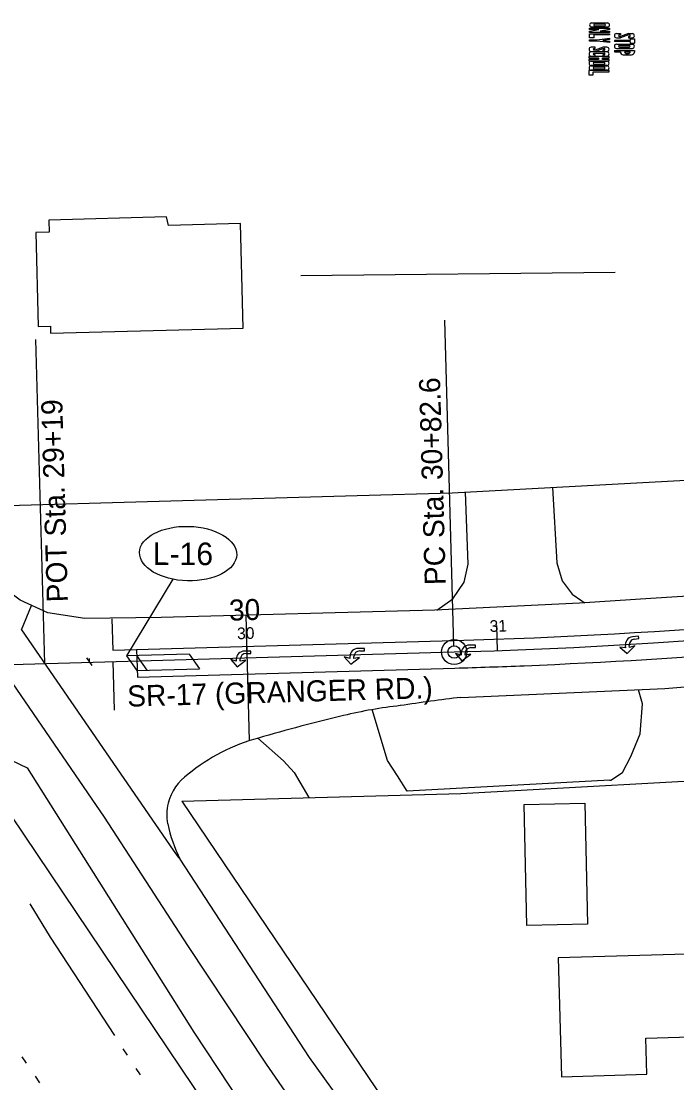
# Model space of a CAD drawing. Extents: x -2233 to 187241, y 4582 to 150524.
# Drawn here: x 103070.3 to 103332, y 58193.5 to 58617.2 of the extents above; entities that cross this region are included whole.
import ezdxf

# ---------------------------------------------------------------- set-up
doc = ezdxf.new("R2010")
doc.units = 0
for name, color, linetype in [('BLDG', 7, 'Continuous'), ('GE_X_CL_100', 7, 'Continuous'), ('GE_X_CL_20', 7, 'Continuous'), ('GE_X_CL_2000', 7, 'Continuous'), ('GE_X_CL_50', 7, 'Continuous'), ('PM_P_Cells', 7, 'Continuous'), ('PM_P_Channelizing_Line', 7, 'Continuous'), ('PM_P_CL_Double_Solid', 7, 'Continuous'), ('PM_P_Stop_Line', 7, 'Continuous'), ('PM_X_CL_Double_Solid', 7, 'Continuous'), ('PV_X_Driveway', 7, 'Continuous'), ('ROAD', 7, 'Continuous'), ('RW_X_Fee_RW', 7, 'Continuous'), ('SC_Scratch2', 7, 'Continuous'), ('SG_P_Detection', 7, 'Continuous'), ('SH_Data', 7, 'Continuous'), ('WATER', 7, 'Continuous')]:
    doc.layers.add(name, color=color, linetype=linetype)

msp = doc.modelspace()

# ---------------------------------------------------------------- linework, layer by layer
at = {"layer": 'BLDG'}
for points in [[(103157.82, 58536.46), (103129.03, 58535.72), (103128.3, 58539.08), (103081.27, 58537.87), (103081.4, 58533.01), (103076.1, 58532.87), (103077.07, 58495.34), (103081.93, 58495.47), (103081.99, 58492.72), (103158.9, 58494.7)], [(103295.24, 58305.14), (103296.36, 58256.85), (103272.17, 58256.29), (103271.05, 58304.59)], [(103286.01, 58195.87), (103320.03, 58196.88), (103319.61, 58211.34), (103355.42, 58212.39), (103354.45, 58245.4), (103284.62, 58243.35)]]:
    msp.add_lwpolyline(points, close=True, dxfattribs=at)
at = {"layer": 'GE_X_CL_100'}
for p, q in [((103243.02, 58367.96), (103239.36, 58497.89)), ((103079.68, 58360.85), (103076.03, 58490.12)), ((103260.46, 58366.01), (103260.1, 58376.01)), ((103160.5, 58363.13), (103160.22, 58373.12)), ((103097.52, 58361.35), (103097.48, 58362.9))]:
    msp.add_line(p, q, dxfattribs=at)
msp.add_circle((103243.1, 58365.46), 5, dxfattribs=at)
at = {"layer": 'GE_X_CL_20'}
for q in [(103243.1, 58365.46), (103103.31, 58299.51)]:
    msp.add_line((103061.64, 58360.34), q, dxfattribs=at)
msp.add_arc((103178.49, 60656.39), 2291.85, 271.61534, 297.032, dxfattribs=at)
at = {"layer": 'GE_X_CL_2000'}
for q in [(103243.1, 58365.46), (103103.31, 58299.51)]:
    msp.add_line((103061.64, 58360.34), q, dxfattribs=at)
msp.add_lwpolyline([(103103.31, 58299.51), (103136.59, 58248.24), (103168.03, 58200.95), (103200, 58154.75)], dxfattribs=at)
msp.add_arc((103178.49, 60656.39), 2291.85, 271.61534, 297.032, dxfattribs=at)
at = {"layer": 'GE_X_CL_50'}
for p, q in [((103260.46, 58366.01), (103260.28, 58371.01)), ((103160.5, 58363.13), (103160.36, 58368.13))]:
    msp.add_line(p, q, dxfattribs=at)
msp.add_circle((103243.1, 58365.46), 2.5, dxfattribs=at)
at = {"layer": 'PM_P_Cells'}
for p, q in [((103297.98, 58616.57), (103299.15, 58616.57)), ((103299.15, 58616.57), (103299.15, 58616.07)), ((103299.15, 58616.07), (103299.15, 58616.57)), ((103299.15, 58616.57), (103303.15, 58616.57)), ((103303.15, 58616.07), (103303.15, 58616.57)), ((103303.15, 58616.57), (103304.31, 58616.57)), ((103303.15, 58616.57), (103303.15, 58616.07)), ((103297.15, 58613.9), (103297.15, 58614.4)), ((103297.15, 58614.4), (103305.15, 58614.4)), ((103297.15, 58613.24), (103300.9, 58613.9)), ((103300.9, 58613.9), (103297.15, 58613.9)), ((103297.15, 58612.74), (103297.15, 58613.24)), ((103305.15, 58612.74), (103297.15, 58612.74)), ((103297.15, 58612.65), (103297.15, 58612.65)), ((103304.31, 58614.9), (103297.98, 58614.9)), ((103303.15, 58616.07), (103299.15, 58616.07)), ((103299.15, 58615.4), (103303.15, 58615.4)), ((103305.15, 58613.9), (103301.4, 58613.24)), ((103301.4, 58613.24), (103305.15, 58613.24)), ((103305.15, 58614.4), (103305.15, 58613.9)), ((103305.15, 58613.24), (103305.15, 58612.74)), ((103305.15, 58612.65), (103305.15, 58612.65)), ((103307.9, 58612.28), (103309.49, 58612.28)), ((103309.49, 58612.28), (103309.49, 58611.78)), ((103312.72, 58612.28), (103309.49, 58611.11)), ((103312.72, 58612.28), (103314.24, 58612.28)), ((103297.15, 58610.57), (103297.15, 58612.24)), ((103297.15, 58612.24), (103305.15, 58612.24)), ((103298.81, 58610.57), (103297.15, 58610.57)), ((103297.15, 58609.32), (103297.15, 58609.82)), ((103297.15, 58609.82), (103300.15, 58609.82)), ((103300.15, 58609.32), (103297.15, 58609.32)), ((103305.15, 58611.74), (103298.81, 58611.74)), ((103298.81, 58611.74), (103298.81, 58610.57)), ((103300.15, 58609.82), (103305.15, 58610.4)), ((103305.15, 58608.74), (103300.15, 58609.32)), ((103305.15, 58609.9), (103302.48, 58609.57)), ((103302.48, 58609.57), (103305.15, 58609.24)), ((103305.15, 58612.24), (103305.15, 58611.74)), ((103305.15, 58610.4), (103305.15, 58609.9)), ((103305.15, 58609.24), (103305.15, 58608.74)), ((103313.4, 58609.57), (103307.07, 58609.57)), ((103307.07, 58609.57), (103307.07, 58609.07)), ((103313.4, 58609.07), (103307.07, 58609.07)), ((103307.07, 58608.07), (103307.07, 58608.07)), ((103307.9, 58610.61), (103309.49, 58610.61)), ((103309.07, 58611.78), (103309.49, 58611.78)), ((103309.07, 58611.11), (103309.49, 58611.11)), ((103312.65, 58611.78), (103309.49, 58610.61)), ((103312.65, 58611.78), (103313.07, 58611.78)), ((103312.65, 58611.11), (103312.65, 58610.61)), ((103312.65, 58611.11), (103313.07, 58611.11)), ((103312.65, 58610.61), (103314.24, 58610.61)), ((103313.4, 58610.15), (103315.07, 58610.15)), ((103313.4, 58610.15), (103313.4, 58609.57)), ((103313.4, 58609.07), (103313.4, 58608.49)), ((103313.4, 58608.49), (103315.07, 58608.49)), ((103315.07, 58610.15), (103315.07, 58608.49)), ((103315.07, 58608.07), (103315.07, 58608.07)), ((103299.35, 58606.86), (103297.77, 58606.86)), ((103297.77, 58605.19), (103299.35, 58605.19)), ((103304.1, 58604.99), (103297.77, 58604.99)), ((103298.93, 58606.36), (103299.35, 58606.36)), ((103299.35, 58605.69), (103298.93, 58605.69)), ((103298.93, 58604.49), (103302.93, 58604.49)), ((103299.35, 58603.82), (103298.93, 58603.82)), ((103302.58, 58606.86), (103299.35, 58605.69)), ((103299.35, 58606.36), (103299.35, 58606.86)), ((103299.35, 58605.19), (103302.52, 58606.36)), ((103299.35, 58603.32), (103299.35, 58603.82)), ((103302.52, 58606.36), (103302.93, 58606.36)), ((103302.52, 58605.69), (103302.52, 58605.19)), ((103302.93, 58605.69), (103302.52, 58605.69)), ((103302.52, 58605.19), (103304.1, 58605.19)), ((103302.52, 58603.82), (103302.52, 58603.32)), ((103302.93, 58603.82), (103302.52, 58603.82)), ((103304.1, 58606.86), (103302.58, 58606.86)), ((103307.07, 58605.53), (103315.07, 58605.53)), ((103307.07, 58605.53), (103307.07, 58605.03)), ((103307.07, 58605.03), (103309.49, 58605.03)), ((103307.9, 58608.03), (103314.24, 58608.03)), ((103307.9, 58606.36), (103314.24, 58606.36)), ((103309.07, 58607.53), (103313.07, 58607.53)), ((103309.07, 58606.86), (103313.07, 58606.86)), ((103309.49, 58605.03), (103309.49, 58605.03)), ((103310.64, 58603.86), (103313.91, 58603.86)), ((103311.15, 58605.03), (103311.15, 58605.03)), ((103311.15, 58605.03), (103313.4, 58605.03)), ((103311.81, 58604.36), (103312.74, 58604.36)), ((103313.4, 58605.03), (103313.4, 58605.02)), ((103315.07, 58605.53), (103315.07, 58604.89)), ((103304.93, 58603.12), (103296.93, 58603.12)), ((103296.93, 58603.12), (103296.93, 58602.62)), ((103296.93, 58602.62), (103300.68, 58602.62)), ((103300.68, 58601.96), (103296.93, 58601.96)), ((103296.93, 58601.96), (103296.93, 58601.46)), ((103296.93, 58601.46), (103304.93, 58601.46)), ((103296.93, 58601.36), (103296.93, 58601.36)), ((103297.77, 58603.32), (103299.35, 58603.32)), ((103297.77, 58601.26), (103298.93, 58601.26)), ((103304.1, 58599.59), (103297.77, 58599.59)), ((103298.93, 58601.26), (103298.93, 58600.76)), ((103298.93, 58601.26), (103302.94, 58601.26)), ((103298.93, 58600.76), (103298.93, 58601.26)), ((103302.97, 58600.76), (103298.93, 58600.76)), ((103298.93, 58600.09), (103302.94, 58600.09)), ((103300.68, 58602.62), (103300.68, 58601.96)), ((103302.35, 58601.96), (103302.35, 58602.62)), ((103302.35, 58602.62), (103304.93, 58602.62)), ((103304.93, 58601.96), (103302.35, 58601.96)), ((103302.52, 58603.32), (103304.1, 58603.32)), ((103302.94, 58601.26), (103304.1, 58601.26)), ((103302.94, 58600.76), (103302.94, 58601.26)), ((103302.94, 58601.26), (103302.94, 58600.76)), ((103304.93, 58602.62), (103304.93, 58603.12)), ((103304.93, 58601.46), (103304.93, 58601.96)), ((103304.93, 58601.36), (103304.93, 58601.36)), ((103304.93, 58597.52), (103296.93, 58597.52)), ((103296.93, 58597.52), (103296.93, 58595.86)), ((103296.93, 58595.86), (103298.6, 58595.86)), ((103297.77, 58599.39), (103298.93, 58599.39)), ((103304.1, 58597.72), (103297.77, 58597.72)), ((103298.6, 58595.86), (103298.6, 58597.02)), ((103298.6, 58597.02), (103304.93, 58597.02)), ((103298.93, 58599.39), (103298.93, 58598.89)), ((103298.93, 58599.39), (103302.93, 58599.39)), ((103298.93, 58598.89), (103298.93, 58599.39)), ((103302.93, 58598.89), (103298.93, 58598.89)), ((103298.93, 58598.22), (103302.93, 58598.22)), ((103302.93, 58599.39), (103304.1, 58599.39)), ((103302.93, 58598.89), (103302.93, 58599.39)), ((103302.93, 58599.39), (103302.93, 58598.89)), ((103304.93, 58597.02), (103304.93, 58597.52)), ((103316.7, 58371.81), (103314.25, 58371.47)), ((103314.99, 58370.57), (103316.84, 58370.82)), ((103316.84, 58370.82), (103316.7, 58371.81)), ((103207.25, 58366.88), (103204.77, 58366.88)), ((103207.25, 58365.88), (103207.25, 58366.88)), ((103251.65, 58368.21), (103249.18, 58368.21)), ((103249.79, 58367.21), (103251.65, 58367.21)), ((103251.65, 58367.21), (103251.65, 58368.21)), ((103309.22, 58367.43), (103309.22, 58367.43)), ((103311.53, 58367.07), (103309.22, 58367.43)), ((103309.22, 58367.43), (103312.16, 58364.8)), ((103311.44, 58367.73), (103311.53, 58367.07)), ((103312.16, 58364.8), (103315.29, 58367.92)), ((103313.12, 58367.28), (103313.02, 58367.98)), ((103315.29, 58367.92), (103313.12, 58367.28)), ((103317.15, 58368.5), (103317.15, 58368.5)), ((103153.88, 58362.5), (103153.88, 58362.5)), ((103156.12, 58361.84), (103153.88, 58362.5)), ((103153.88, 58362.5), (103156.44, 58359.5)), ((103156.12, 58362.5), (103156.12, 58361.84)), ((103157.72, 58361.84), (103157.72, 58362.54)), ((103161.88, 58365.84), (103159.4, 58365.84)), ((103160.02, 58364.84), (103161.88, 58364.84)), ((103161.88, 58364.84), (103161.88, 58365.84)), ((103161.88, 58362.5), (103161.88, 58362.5)), ((103199.25, 58363.55), (103199.25, 58363.55)), ((103201.49, 58362.88), (103199.25, 58363.55)), ((103199.25, 58363.55), (103201.81, 58360.55)), ((103201.49, 58363.55), (103201.49, 58362.88)), ((103201.81, 58360.55), (103205.33, 58363.22)), ((103203.09, 58362.88), (103203.09, 58363.59)), ((103205.33, 58363.22), (103203.09, 58362.88)), ((103205.38, 58365.88), (103207.25, 58365.88)), ((103207.25, 58363.55), (103207.25, 58363.55)), ((103243.65, 58364.88), (103243.65, 58364.88)), ((103245.89, 58364.21), (103243.65, 58364.88)), ((103243.65, 58364.88), (103246.21, 58361.88)), ((103245.89, 58364.88), (103245.89, 58364.21)), ((103246.21, 58361.88), (103249.73, 58364.54)), ((103247.49, 58364.21), (103247.49, 58364.91)), ((103249.73, 58364.54), (103247.49, 58364.21)), ((103251.65, 58364.88), (103251.65, 58364.88)), ((103156.44, 58359.5), (103159.96, 58362.17)), ((103159.96, 58362.17), (103157.72, 58361.84))]:
    msp.add_line(p, q, dxfattribs=at)
for centre, radius, start, end in [((103297.98, 58615.74), 0.833, 90, 270), ((103304.31, 58615.74), 0.833, 270, 90), ((103299.15, 58615.74), 0.333, 90, 270), ((103303.15, 58615.74), 0.333, 270, 90), ((103307.9, 58611.45), 0.833, 90, 270), ((103314.24, 58611.45), 0.833, 270, 90), ((103309.07, 58611.45), 0.333, 90, 270), ((103313.07, 58611.45), 0.333, 269.3983, 90), ((103297.77, 58606.02), 0.833, 90, 270), ((103297.77, 58604.16), 0.833, 90, 270), ((103298.93, 58606.02), 0.333, 90, 270), ((103298.93, 58604.16), 0.333, 90, 270), ((103302.93, 58606.02), 0.333, 269.3983, 90), ((103302.93, 58604.16), 0.333, 269.3983, 90.6017), ((103304.1, 58606.02), 0.833, 270, 90), ((103304.1, 58604.16), 0.833, 270, 90), ((103307.9, 58607.2), 0.833, 90, 270), ((103309.07, 58607.2), 0.333, 90, 270), ((103310.65, 58605.03), 1.17, 180.001, 269.5669), ((103311.82, 58605.03), 0.667, 180, 269.4271), ((103312.74, 58605.03), 0.667, 269.4271, 359.9989), ((103313.07, 58607.2), 0.333, 270, 90), ((103313.91, 58605.03), 1.17, 269.997, 352.9317), ((103314.24, 58607.2), 0.833, 270, 90), ((103297.77, 58600.42), 0.833, 90, 270), ((103298.93, 58600.42), 0.333, 90, 270), ((103302.94, 58600.43), 0.333, 269.3983, 90.6017), ((103304.1, 58600.42), 0.833, 270, 90), ((103297.77, 58598.56), 0.833, 90, 270), ((103298.93, 58598.56), 0.333, 90, 270), ((103302.93, 58598.56), 0.333, 269.3983, 90.6017), ((103304.1, 58598.56), 0.833, 270, 90), ((103314.69, 58368.22), 3.28, 97.7092, 188.6177), ((103204.77, 58363.6), 3.28, 90, 180.9085), ((103249.18, 58364.93), 3.28, 90, 180.9085), ((103249.79, 58364.91), 2.3, 90, 180), ((103315.3, 58368.29), 2.3, 97.7092, 187.7092), ((103159.4, 58362.55), 3.28, 90, 180.9085), ((103160.02, 58362.54), 2.3, 90, 180), ((103205.38, 58363.59), 2.3, 90, 180)]:
    msp.add_arc(centre, radius, start, end, dxfattribs=at)
at = {"layer": 'PM_P_Channelizing_Line'}
msp.add_line((103106.83, 58366.17), (103242.97, 58370.01), dxfattribs=at)
msp.add_arc((103178.49, 60656.39), 2287.3, 271.61534, 278.042, dxfattribs=at)
at = {"layer": 'PM_P_CL_Double_Solid'}
msp.add_arc((103178.5, 60657.41), 2299.29, 271.61534, 272.30706, dxfattribs=at)
at = {"layer": 'PM_P_Stop_Line'}
for p, q in [((103106.49, 58378.63), (103106.83, 58366.17)), ((103116.33, 58366.43), (103116.62, 58355.46))]:
    msp.add_line(p, q, dxfattribs=at)
at = {"layer": 'PM_X_CL_Double_Solid'}
msp.add_line((103116.62, 58355.46), (103243.31, 58359.03), dxfattribs=at)
msp.add_arc((103178.5, 60657.41), 2299.29, 272.30706, 282.04395, dxfattribs=at)
at = {"layer": 'PV_X_Driveway'}
for p, q in [((103216.44, 58322.08), (103210.43, 58342.45)), ((103220.47, 58316.07), (103216.44, 58322.08)), ((103224.31, 58309.96), (103220.47, 58316.07)), ((103305.28, 58314.29), (103224.31, 58309.96))]:
    msp.add_line(p, q, dxfattribs=at)
for points in [[(103282.41, 58431.15), (103284.05, 58401.02), (103286.17, 58393.84), (103290.16, 58388.53), (103294.14, 58385.87), (103295.24, 58385.05)], [(103236.23, 58382.16), (103242.63, 58386.67), (103247.14, 58393.31), (103248.74, 58400.49), (103247.6, 58429.23)], [(103305.28, 58314.29), (103305.71, 58314.3), (103310.26, 58317.33), (103313.6, 58323.71), (103317.39, 58332.82), (103318.3, 58344.81), (103316.76, 58350.4)], [(103164.74, 58331.03), (103175.01, 58321.96), (103179.17, 58317.33), (103185.04, 58307.31)]]:
    msp.add_lwpolyline(points, dxfattribs=at)
at = {"layer": 'ROAD'}
for p, q in [((103070.39, 58374.34), (103074.37, 58384.04)), ((103161.43, 58330.06), (103160.02, 58380.08)), ((103070.39, 58374.34), (103130.87, 58286.36)), ((103096.3, 58363.13), (103098.44, 58360.02))]:
    msp.add_line(p, q, dxfattribs=at)
for points in [[(103637.3, 58428.9), (103588.89, 58419.2), (103547.51, 58411.74), (103515.1, 58407.04), (103477.29, 58401.7), (103420.29, 58394.73), (103365.86, 58389.66), (103321.56, 58386.78), (103293.08, 58384.91), (103235.45, 58382.12), (103126.17, 58379.16), (103095.59, 58378.8), (103080.81, 58381.1), (103069.89, 58386.09), (103062.93, 58391.35), (103055.38, 58398.19), (103035.63, 58429.95), (102935.98, 58573.91), (102867.66, 58678.31), (102808.51, 58765.03), (102746.03, 58853.95), (102718.48, 58895.99)], [(103245.8, 58347.35), (103327.17, 58350.85), (103356.15, 58353.22), (103379.58, 58355.97), (103408.49, 58358.63), (103440.63, 58361.68), (103468.3, 58364.98), (103499.28, 58368.52), (103533.71, 58373.47), (103568.7, 58379), (103597.08, 58384.09), (103630.69, 58390.83)], [(102597.24, 58327.52), (102701.03, 58330.14), (102825.23, 58331.95), (102902.95, 58331.48), (102981.98, 58330.89), (103021.42, 58331.14), (103033.45, 58330.46), (103043.25, 58329.27), (103051.61, 58327.55), (103062.95, 58323.85), (103072.64, 58319.26), (103139.1, 58213.69), (103210.4, 58105.87)], [(103214.66, 58162.91), (103185.4, 58203.57), (103133.66, 58282.69)]]:
    msp.add_lwpolyline(points, dxfattribs=at)
for centre, radius, start, end in [((103329.92, 57644.05), 708.31, 96.81991, 98.79559), ((103241.09, 58165.46), 179.63, 96.2265, 103.5648), ((103358.88, 57666.01), 692.78, 103.34625, 106.25741), ((103184.24, 58259.14), 74.49, 105.0203, 129.4701), ((103148.32, 58300.22), 20.01, 124.8443, 166.056), ((103147.43, 58300.56), 19.07, 166.4087, 191.0962), ((103189.35, 58310.05), 62.04, 192.2425, 206.1608), ((103157.59, 58303.78), 31.89, 213.0699, 221.3874)]:
    msp.add_arc(centre, radius, start, end, dxfattribs=at)
at = {"layer": 'RW_X_Fee_RW'}
for p, q in [((103056.99, 58313.64), (103194.45, 58109.63)), ((103134.36, 58305.91), (103245.74, 58308.99))]:
    msp.add_line(p, q, dxfattribs=at)
for points in [[(103242.35, 58428.94), (103355.26, 58435.16), (103361.14, 58435.48), (103479.41, 58448.36), (103596.83, 58467.54)], [(103055.48, 58423.65), (103204.38, 58427.86), (103242.35, 58428.94)], [(103245.74, 58308.99), (103370.94, 58315.88), (103373.66, 58316.18), (103495.59, 58329.46), (103619.33, 58349.67)], [(103134.36, 58305.91), (103222.17, 58175.86), (103276.43, 58095.32)]]:
    msp.add_lwpolyline(points, dxfattribs=at)
at = {"layer": 'SC_Scratch2'}
msp.add_line((103107.51, 58342.2), (103106.96, 58361.62), dxfattribs=at)
at = {"layer": 'SG_P_Detection'}
for p, q in [((103181.95, 58515.72), (103307.38, 58517.12)), ((103137.27, 58364.63), (103112.27, 58363.96)), ((103112.27, 58363.96), (103116.43, 58358.07)), ((103116.27, 58364.07), (103120.43, 58358.18)), ((103137.27, 58364.63), (103141.43, 58358.74)), ((103116.43, 58358.07), (103141.43, 58358.74))]:
    msp.add_line(p, q, dxfattribs=at)
at = {"layer": 'SH_Data'}
msp.add_line((103130.72, 58394.51), (103112.27, 58363.96), dxfattribs=at)
msp.add_ellipse((103136.88, 58404.72), major_axis=(19.39, -0.49), ratio=0.560859, dxfattribs=at)
at = {"layer": 'WATER'}
for p, q in [((103112.7, 58204.49), (103110.99, 58207.11)), ((103070.52, 58203.86), (103072.28, 58201.28)), ((103117.83, 58196.64), (103116.13, 58199.26)), ((103075.79, 58196.11), (103077.54, 58193.52))]:
    msp.add_line(p, q, dxfattribs=at)
msp.add_lwpolyline([(103107.57, 58212.34), (103081.88, 58251.6), (103073.8, 58264.91)], dxfattribs=at)

# ---------------------------------------------------------------- texts
at = {"layer": 'GE_X_CL_100'}
for s, height, rotation, p in [('PC Sta. 30+82.6', 8.42, 91.6153, (103239.78, 58392.26)), ('POT Sta. 29+19', 8.42, 91.6153, (103088.9, 58385.4)), ('30', 8.4, 1.6153, (103153.32, 58377.93))]:
    msp.add_text(s, height=height, rotation=rotation, dxfattribs=at).set_placement(p)
at = {"layer": 'GE_X_CL_50'}
for s, height, rotation, p in [('30', 4.68, 1.6153, (103156.48, 58370.52)), ('31', 4.68, 2.0496, (103257.33, 58373.41)), ('SR-17 (GRANGER RD.)', 8.42, 1.6067, (103112.68, 58343.61))]:
    msp.add_text(s, height=height, rotation=rotation, dxfattribs=at).set_placement(p)
at = {"layer": 'SH_Data'}
msp.add_text('L-16', height=9, rotation=359.8172, dxfattribs=at).set_placement((103122.75, 58400.19))

doc.saveas('drawing.dxf')
